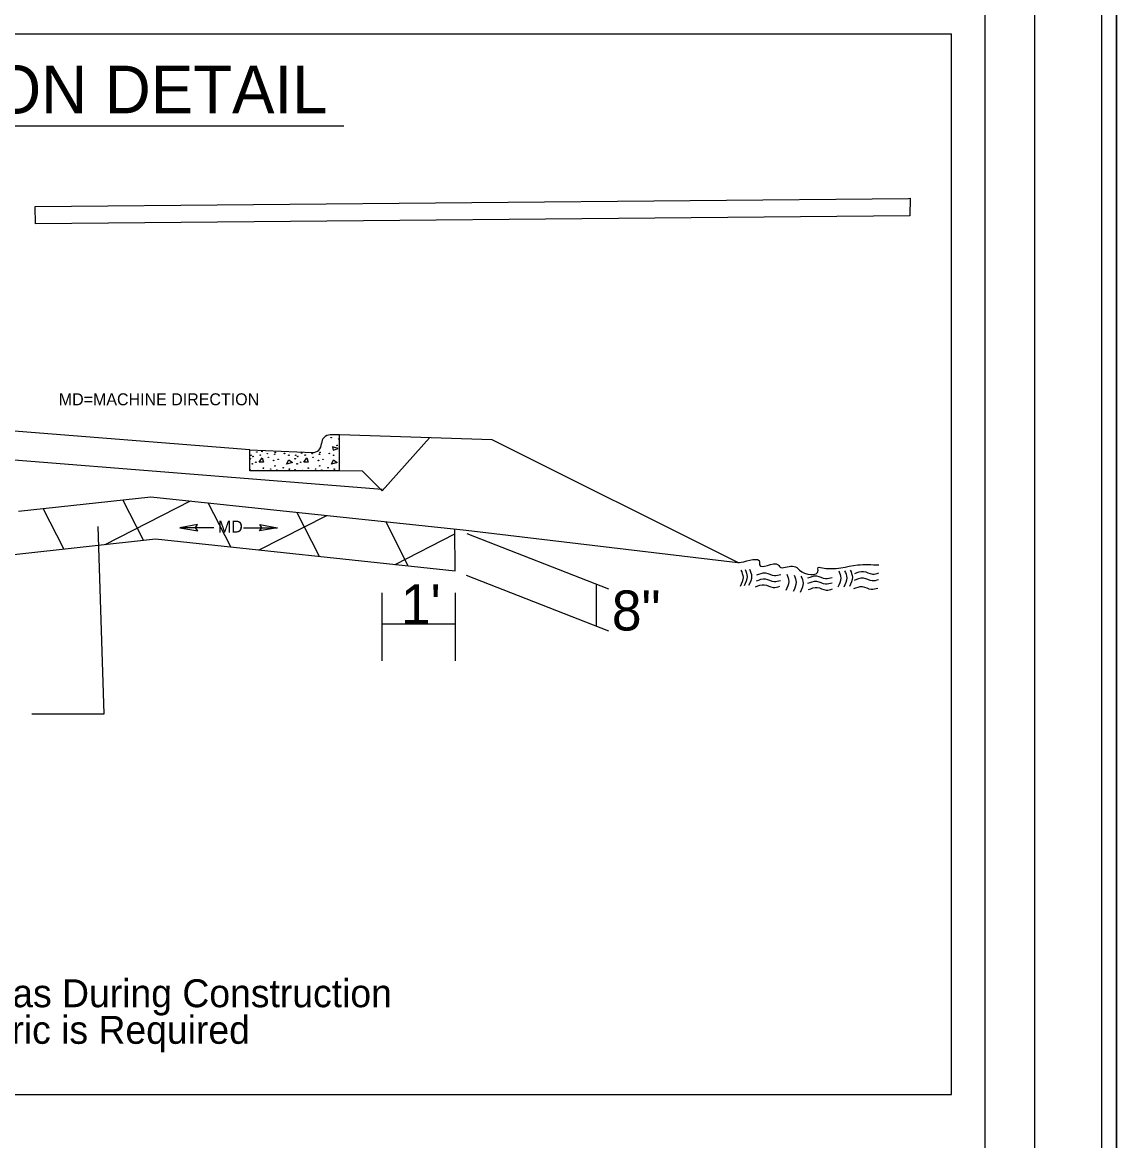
# Model space of a CAD drawing. Extents: x 2294342 to 2294901, y 719427 to 719941.
# Drawn here: x 2294739.6 to 2294794.5, y 719839.8 to 719895.9 of the extents above; entities that cross this region are included whole.
import ezdxf

# ---------------------------------------------------------------- set-up
doc = ezdxf.new("R2010")
doc.units = 0
for name, color, linetype in [('Default', 7, 'Continuous'), ('Old_Level_11', 7, 'Continuous'), ('Prop Dimension', 7, 'Continuous'), ('Prop Shade Light', 7, 'Continuous'), ('Prop Terminator CELL', 7, 'Continuous'), ('Prop XS Undercut Exc', 7, 'Continuous'), ('Raster_Level_2', 7, 'Continuous'), ('Sheet Plot Border Inside CELL', 7, 'Continuous'), ('Sheet Plot Border Outside CELL', 7, 'Continuous'), ('Sheet Typical CELL', 7, 'Continuous'), ('Typical Detail Wedge2 CELL', 7, 'Continuous'), ('Typical Hinge Slope Interstate CELL', 7, 'Continuous'), ('Typical Pavement Slope CELL', 7, 'Continuous'), ('Typical Text General CELL', 7, 'Continuous')]:
    doc.layers.add(name, color=color, linetype=linetype)

msp = doc.modelspace()

# ---------------------------------------------------------------- linework, layer by layer
at = {"layer": 'Default'}
msp.add_line((2294794.524, 719936.169), (2294794.524, 719716.169), dxfattribs=at)
msp.add_lwpolyline([(2294454.524, 719936.169), (2294794.524, 719936.169), (2294794.524, 719716.169), (2294454.524, 719716.169)], close=True, dxfattribs=at)
msp.add_lwpolyline([(2294454.524, 719936.169), (2294794.524, 719936.169), (2294794.524, 719716.169), (2294454.524, 719716.169)], close=True, dxfattribs=at)
at = {"layer": 'Old_Level_11'}
for p, q in [((2294743.738, 719861.172), (2294743.432, 719870.574)), ((2294761.934, 719870.213), (2294769.026, 719867.438)), ((2294761.889, 719868.136), (2294769.032, 719865.342)), ((2294757.665, 719867.249), (2294757.665, 719863.828)), ((2294761.338, 719867.249), (2294761.338, 719863.828)), ((2294768.42, 719867.676), (2294768.42, 719865.581)), ((2294757.711, 719865.682), (2294761.338, 719865.682)), ((2294740.111, 719861.172), (2294743.738, 719861.172))]:
    msp.add_line(p, q, dxfattribs=at)
at = {"layer": 'Prop Dimension'}
for p, q in [((2294749.232, 719870.513), (2294747.524, 719870.513)), ((2294750.73, 719870.513), (2294752.438, 719870.513))]:
    msp.add_line(p, q, dxfattribs=at)
at = {"layer": 'Prop Shade Light'}
msp.add_lwpolyline([(2294740.281, 719886.628), (2294784.079, 719887.03), (2294784.164, 719887.045), (2294784.158, 719886.149), (2294740.289, 719885.76)], close=True, dxfattribs=at)
at = {"layer": 'Prop Terminator CELL'}
for points in [[(2294748.424, 719870.668), (2294747.524, 719870.513), (2294748.429, 719870.353), (2294748.314, 719870.513)], [(2294751.538, 719870.668), (2294752.438, 719870.513), (2294751.533, 719870.353), (2294751.648, 719870.513)]]:
    msp.add_lwpolyline(points, close=True, dxfattribs=at)
at = {"layer": 'Prop XS Undercut Exc'}
for p, q in [((2294743.793, 719869.675), (2294748.071, 719871.855)), ((2294745.706, 719869.882), (2294744.67, 719871.915)), ((2294750.087, 719869.545), (2294748.958, 719871.761)), ((2294741.718, 719869.449), (2294740.682, 719871.482)), ((2294751.502, 719869.395), (2294754.906, 719871.13)), ((2294754.537, 719869.073), (2294753.408, 719871.289)), ((2294758.987, 719868.601), (2294757.857, 719870.817)), ((2294739.202, 719869.176), (2294746.304, 719869.947)), ((2294746.304, 719869.947), (2294761.338, 719868.351)), ((2294758.336, 719868.67), (2294761.333, 719870.198)), ((2294761.338, 719868.351), (2294761.333, 719870.448))]:
    msp.add_line(p, q, dxfattribs=at)
at = {"layer": 'Raster_Level_2'}
msp.add_line((2294703.739, 719890.666), (2294755.765, 719890.666), dxfattribs=at)
at = {"layer": 'Sheet Plot Border Inside CELL'}
msp.add_lwpolyline([(2294790.424, 719931.679), (2294457.124, 719931.679), (2294457.124, 719720.659), (2294790.424, 719720.659)], close=True, dxfattribs=at)
at = {"layer": 'Sheet Plot Border Outside CELL'}
for points in [[(2294793.79, 719941.133), (2294456.99, 719941.133), (2294456.99, 719721.133), (2294793.79, 719721.133)], [(2294794.524, 719936.169), (2294454.524, 719936.169), (2294454.524, 719716.169), (2294794.524, 719716.169)]]:
    msp.add_lwpolyline(points, close=True, dxfattribs=at)
at = {"layer": 'Sheet Typical CELL'}
msp.add_lwpolyline([(2294787.924, 719931.169), (2294487.924, 719931.169), (2294487.924, 719721.169), (2294787.924, 719721.169)], close=True, dxfattribs=at)
at = {"layer": 'Typical Detail Wedge2 CELL'}
msp.add_line((2294786.234, 719842.089), (2294786.234, 719895.279), dxfattribs=at)
at = {"layer": 'Typical Pavement Slope CELL'}
for p, q in [((2294751.037, 719874.415), (2294729.856, 719876.094)), ((2294755.536, 719875.165), (2294755.068, 719875.165)), ((2294755.536, 719873.365), (2294755.536, 719875.165)), ((2294763.194, 719874.927), (2294755.536, 719875.165)), ((2294757.675, 719872.355), (2294760.062, 719875.024)), ((2294757.681, 719872.432), (2294729.741, 719874.648)), ((2294754.636, 719874.714), (2294754.636, 719874.733)), ((2294755.193, 719874.565), (2294755.223, 719874.402)), ((2294755.471, 719874.484), (2294755.193, 719874.565)), ((2294755.223, 719874.402), (2294755.471, 719874.484)), ((2294775.527, 719868.761), (2294763.194, 719874.927)), ((2294751.037, 719873.365), (2294751.037, 719874.415)), ((2294751.037, 719874.415), (2294754.187, 719874.283)), ((2294751.506, 719873.796), (2294751.661, 719874.012)), ((2294751.661, 719874.012), (2294751.723, 719873.807)), ((2294752.884, 719873.704), (2294752.996, 719873.91)), ((2294752.996, 719873.91), (2294753.182, 719873.775)), ((2294753.755, 719873.796), (2294753.909, 719874.012)), ((2294753.909, 719874.012), (2294753.971, 719873.807)), ((2294755.131, 719873.704), (2294755.244, 719873.91)), ((2294755.244, 719873.91), (2294755.429, 719873.775)), ((2294755.536, 719873.365), (2294751.037, 719873.365)), ((2294751.723, 719873.807), (2294751.506, 719873.796)), ((2294753.182, 719873.775), (2294752.884, 719873.704)), ((2294753.971, 719873.807), (2294753.755, 719873.796)), ((2294755.429, 719873.775), (2294755.131, 719873.704)), ((2294756.688, 719873.342), (2294755.536, 719873.365)), ((2294756.688, 719873.342), (2294757.675, 719872.355)), ((2294739.439, 719871.348), (2294746.074, 719872.067)), ((2294746.074, 719872.067), (2294761.9, 719870.388)), ((2294761.9, 719870.388), (2294775.527, 719868.761))]:
    msp.add_line(p, q, dxfattribs=at)
for centre in [(2294755.122, 719875.028), (2294755.512, 719874.966), (2294755.42, 719874.638), (2294751.067, 719873.972), (2294751.097, 719874.146), (2294751.198, 719874.085), (2294751.394, 719874.309), (2294751.568, 719874.156), (2294751.65, 719874.34), (2294751.918, 719874.227), (2294751.969, 719874.043), (2294752.236, 719873.889), (2294752.288, 719874.198), (2294752.318, 719874.288), (2294752.462, 719873.941), (2294752.781, 719874.237), (2294752.997, 719874.146), (2294753.315, 719873.972), (2294753.346, 719874.146), (2294753.447, 719874.085), (2294753.642, 719874.253), (2294753.816, 719874.156), (2294754.166, 719874.227), (2294754.217, 719874.043), (2294754.485, 719873.889), (2294754.536, 719874.198), (2294754.567, 719874.288), (2294754.711, 719873.941), (2294755.029, 719874.237), (2294755.245, 719874.146), (2294751.056, 719873.416), (2294751.169, 719873.714), (2294751.342, 719873.797), (2294751.435, 719873.376), (2294751.722, 719873.499), (2294752.092, 719873.458), (2294752.298, 719873.612), (2294752.401, 719873.406), (2294752.719, 719873.519), (2294753.027, 719873.448), (2294753.305, 719873.416), (2294753.418, 719873.714), (2294753.591, 719873.797), (2294753.683, 719873.376), (2294753.971, 719873.499), (2294754.341, 719873.458), (2294754.546, 719873.612), (2294754.649, 719873.406), (2294754.968, 719873.519), (2294755.276, 719873.448)]:
    msp.add_circle(centre, 0.0144, dxfattribs=at)
for centre, start, end in [((2294755.068, 719874.733), 90, 180), ((2294754.205, 719874.714), 267.6155, 0)]:
    msp.add_arc(centre, 0.431, start, end, dxfattribs=at)
for points in [[(2294775.527, 719868.761), (2294775.685, 719868.778), (2294776.617, 719868.778), (2294776.617, 719868.645), (2294777.548, 719868.645), (2294777.681, 719868.512), (2294777.814, 719868.512), (2294778.48, 719868.512), (2294778.613, 719868.379), (2294779.544, 719868.379), (2294779.544, 719868.512), (2294779.677, 719868.512), (2294781.54, 719868.645), (2294782.601, 719868.645)], [(2294775.678, 719868.386), (2294775.782, 719868.029), (2294775.633, 719867.567)], [(2294775.887, 719868.416), (2294775.991, 719868.059), (2294775.842, 719867.596)], [(2294776.11, 719868.431), (2294776.215, 719868.073), (2294776.065, 719867.611)], [(2294776.475, 719868.14), (2294776.908, 719868.245), (2294777.355, 719868.111), (2294777.682, 719868.17)], [(2294780.581, 719868.342), (2294780.685, 719867.984), (2294780.536, 719867.522)], [(2294780.879, 719868.357), (2294780.983, 719867.999), (2294780.834, 719867.537)], [(2294781.162, 719868.386), (2294781.266, 719868.029), (2294781.117, 719867.567)], [(2294781.393, 719868.215), (2294781.826, 719868.319), (2294782.273, 719868.185), (2294782.601, 719868.245)], [(2294776.46, 719867.842), (2294776.893, 719867.947), (2294777.34, 719867.812), (2294777.668, 719867.872)], [(2294777.973, 719868.178), (2294778.077, 719867.82), (2294777.928, 719867.358)], [(2294778.346, 719868.133), (2294778.45, 719867.775), (2294778.301, 719867.313)], [(2294778.688, 719868.088), (2294778.793, 719867.731), (2294778.644, 719867.269)], [(2294779.039, 719867.991), (2294779.471, 719868.096), (2294779.918, 719867.962), (2294780.246, 719868.021)], [(2294779.039, 719867.723), (2294779.471, 719867.827), (2294779.918, 719867.693), (2294780.246, 719867.753)], [(2294781.378, 719867.887), (2294781.811, 719867.991), (2294782.258, 719867.857), (2294782.586, 719867.917)], [(2294776.416, 719867.544), (2294776.848, 719867.649), (2294777.295, 719867.514), (2294777.623, 719867.574)], [(2294779.069, 719867.41), (2294779.501, 719867.514), (2294779.948, 719867.38), (2294780.276, 719867.44)], [(2294781.334, 719867.455), (2294781.766, 719867.559), (2294782.213, 719867.425), (2294782.541, 719867.485)]]:
    msp.add_spline(points, degree=3, dxfattribs=at)
at = {"layer": 'Typical Text General CELL'}
for p, q in [((2294686.486, 719895.279), (2294786.234, 719895.279)), ((2294686.486, 719842.089), (2294786.234, 719842.089))]:
    msp.add_line(p, q, dxfattribs=at)

# ---------------------------------------------------------------- texts
at = {"layer": 'Raster_Level_2'}
msp.add_text(' UNDERCUT EXCAVATION DETAIL', height=2.38712, rotation=360, dxfattribs=at).set_placement((2294702.619, 719891.299))
at = {"layer": 'Typical Hinge Slope Interstate CELL'}
for s, p in [('MD=MACHINE DIRECTION', (2294741.459, 719876.653)), ('MD', (2294749.442, 719870.269))]:
    msp.add_text(s, height=0.6, dxfattribs=at).set_placement(p)
at = {"layer": 'Typical Pavement Slope CELL'}
for s, height, p in [("1'", 2.0081, (2294758.614, 719865.661)), ('8"', 2.0081, (2294769.2, 719865.357)), ('Contractor Should Investigate These Areas During Construction', 1.4, (2294705.305, 719846.46)), ('to Determine if Stabilization Fabric is Required', 1.4, (2294712.547, 719844.625))]:
    msp.add_text(s, height=height, dxfattribs=at).set_placement(p)

doc.saveas('drawing.dxf')
